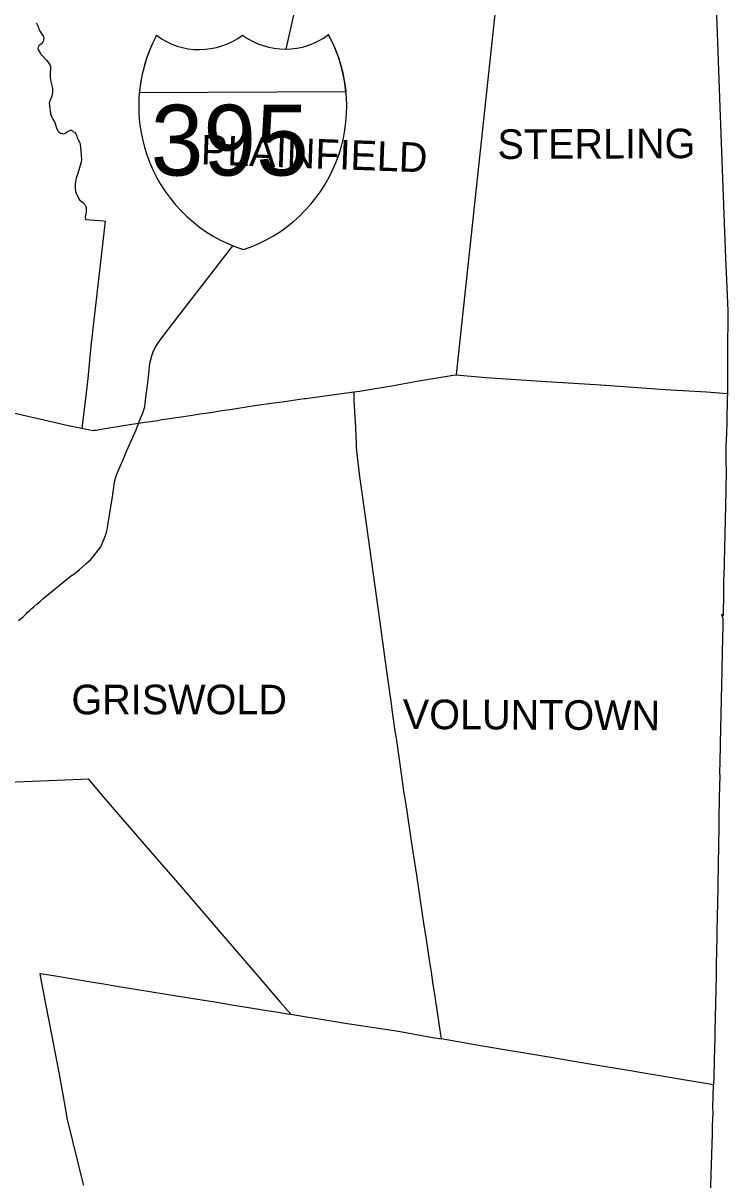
# Model space of a CAD drawing. Extents: x 0 to 2603, y -226 to 830.
# Drawn here: x 329.1 to 361.3, y 575 to 627.8 of the extents above; entities that cross this region are included whole.
import ezdxf

# ---------------------------------------------------------------- set-up
doc = ezdxf.new("R2010")
doc.units = 0
for name, color, linetype in [('CT_TSH_Map_Interstate_Roads', 7, 'Continuous'), ('CT_TSH_Map_Town_Limits', 7, 'Continuous'), ('CT_TSH_Map_Town_Text', 7, 'Continuous')]:
    doc.layers.add(name, color=color, linetype=linetype)

msp = doc.modelspace()

# ---------------------------------------------------------------- linework, layer by layer
at = {"layer": 'CT_TSH_Map_Interstate_Roads'}
msp.add_line((343.877, 624.637), (334.444, 624.598), dxfattribs=at)
for points in [[(341.147, 626.584), (341.673, 628.952), (341.736, 629.234), (341.778, 629.422), (341.809, 629.562)], [(334.875, 611.773), (334.931, 612.252), (334.964, 612.431), (335.01, 612.596), (335.073, 612.767), (335.132, 612.904), (335.198, 613.022), (335.3, 613.181), (335.65, 613.651), (338.704, 617.616)], [(334.718, 610.441), (334.815, 611.26), (334.875, 611.773)], [(334.617, 610.034), (334.694, 610.27), (334.718, 610.441)], [(333.36, 607.015), (333.42, 607.197), (333.748, 607.969), (333.882, 608.272), (334.099, 608.776), (334.3, 609.219), (334.451, 609.625), (334.497, 609.755), (334.586, 609.945), (334.617, 610.034)], [(333.2, 606.063), (333.252, 606.375), (333.278, 606.586), (333.3, 606.74), (333.36, 607.015)], [(333.078, 605.323), (333.2, 606.063)], [(332.989, 604.729), (333.013, 604.863)], [(333.013, 604.863), (333.078, 605.323)], [(332.712, 603.953), (332.795, 604.141), (332.894, 604.393), (332.95, 604.551), (332.989, 604.729)], [(331.465, 602.649), (331.714, 602.847), (332.019, 603.112), (332.217, 603.29), (332.367, 603.464), (332.682, 603.881), (332.712, 603.953)], [(330.474, 601.848), (331.198, 602.44)], [(331.198, 602.44), (331.354, 602.574), (331.383, 602.584)], [(331.383, 602.584), (331.465, 602.649)], [(329.901, 601.371), (330.05, 601.501), (330.474, 601.848)], [(329.298, 600.838), (329.349, 600.891), (329.428, 600.96), (329.541, 601.059), (329.631, 601.139)], [(329.631, 601.139), (329.785, 601.272)], [(329.785, 601.272), (329.901, 601.371)], [(328.928, 600.519), (329.144, 600.689), (329.181, 600.72), (329.298, 600.838)]]:
    msp.add_lwpolyline(points, dxfattribs=at)
for centre, radius, start, end in [((341.281, 623.978), 6.864, 151.8748, 252.2637), ((341.29, 623.974), 6.874, 151.8748, 174.7861), ((337.182, 629.83), 3.265, 233.2263, 307.1377), ((341.099, 629.848), 3.264, 233.3979, 307.1378), ((337.038, 623.958), 6.864, 288.272, 28.6609), ((337.047, 623.954), 6.864, 5.7168, 28.6609)]:
    msp.add_arc(centre, radius, start, end, dxfattribs=at)
at = {"layer": 'CT_TSH_Map_Town_Limits'}
for points in [[(360.247, 642.422), (360.282, 641.586), (360.297, 641.436), (360.382, 638.912), (360.476, 636.7), (360.573, 634.07), (360.626, 632.595), (360.674, 630.705), (360.925, 623.943), (361.148, 617.86), (361.184, 617.067), (361.24, 615.712), (361.288, 614.642), (361.267, 612.67), (361.271, 612.118), (361.268, 611.721), (361.271, 611.425), (361.264, 610.854)], [(351.958, 641.006), (351.841, 639.872), (351.725, 638.728), (351.597, 637.349), (351.525, 636.595), (351.059, 631.882), (348.901, 611.736), (348.901, 611.705)], [(329.735, 627.773), (329.778, 627.709), (329.823, 627.614), (329.859, 627.499), (329.914, 627.385), (330.056, 627.176), (330.072, 627.148), (330.083, 627.118), (330.087, 627.084), (330.081, 627.008), (330.062, 626.949), (330.05, 626.918), (330.005, 626.857), (329.975, 626.827), (329.878, 626.748), (329.862, 626.729), (329.831, 626.668), (329.821, 626.62), (329.864, 626.51), (329.939, 626.379), (329.973, 626.33), (330.005, 626.306), (330.219, 626.066), (330.333, 625.918), (330.379, 625.834), (330.395, 625.788), (330.395, 625.75), (330.397, 625.679), (330.377, 625.488), (330.382, 625.291), (330.408, 625.111), (330.472, 624.87), (330.486, 624.785), (330.489, 624.712), (330.481, 624.577), (330.445, 624.414), (330.432, 624.378), (330.362, 624.242), (330.34, 624.174), (330.331, 624.105), (330.342, 624.016), (330.368, 623.857), (330.37, 623.776), (330.391, 623.638), (330.418, 623.552), (330.452, 623.475), (330.494, 623.395), (330.571, 623.269), (330.594, 623.224), (330.654, 623.042), (330.665, 622.999), (330.732, 622.854), (330.771, 622.808), (330.855, 622.755), (330.934, 622.728), (330.98, 622.723), (331.028, 622.734), (331.153, 622.806), (331.237, 622.864), (331.299, 622.884), (331.326, 622.887), (331.358, 622.882), (331.38, 622.863), (331.481, 622.796), (331.511, 622.772), (331.552, 622.721), (331.567, 622.695), (331.596, 622.614), (331.615, 622.549)], [(331.615, 622.549), (331.628, 622.51), (331.662, 622.439), (331.721, 622.337), (331.732, 622.312), (331.744, 622.241), (331.774, 621.927), (331.798, 621.751), (331.8, 621.536), (331.786, 621.445), (331.744, 621.268), (331.716, 621.162), (331.678, 621.063), (331.602, 620.82), (331.578, 620.776), (331.526, 620.53), (331.513, 620.409), (331.514, 620.245), (331.54, 620.086), (331.562, 620.011), (331.634, 619.841), (331.668, 619.782), (331.722, 619.716), (331.777, 619.665), (331.862, 619.582), (331.901, 619.549), (331.954, 619.496), (331.991, 619.439), (332.006, 619.4), (332.017, 619.359), (332.02, 619.228), (332.013, 619.192), (332.013, 619.152), (331.984, 619.008), (331.974, 618.925), (331.986, 618.83), (331.999, 618.815), (332.199, 618.801), (332.817, 618.747), (332.884, 618.742), (332.235, 613.038), (332.092, 611.555), (332.012, 610.897), (331.819, 609.272)], [(348.901, 611.705), (348.668, 611.674), (347.108, 611.421), (345.963, 611.207), (345.586, 611.144), (345.02, 611.05), (344.486, 610.965), (344.221, 610.931)], [(361.264, 610.854), (360.314, 610.927), (358.428, 611.045), (355.488, 611.249), (353.765, 611.357), (353, 611.407), (350.252, 611.589), (348.901, 611.705)], [(344.221, 610.931), (343.236, 610.796), (342.019, 610.627), (341.964, 610.622), (341.371, 610.537), (340.957, 610.475), (340.564, 610.425), (339.703, 610.305), (338.592, 610.132), (338.451, 610.107), (338.122, 610.062), (337.794, 610.012), (337.581, 609.977), (337.205, 609.926), (336.876, 609.87), (336.248, 609.774), (335.707, 609.695), (335.473, 609.665), (335.294, 609.633), (334.948, 609.587), (334.843, 609.568), (334.675, 609.545), (334.607, 609.53), (333.816, 609.408), (332.886, 609.256), (332.612, 609.219), (332.489, 609.192), (332.406, 609.181), (332.349, 609.179), (332.322, 609.167), (332.193, 609.196), (331.819, 609.272)], [(344.221, 610.931), (344.233, 610.597), (344.233, 610.57), (344.273, 609.792), (344.282, 609.604), (344.328, 608.624), (344.336, 608.422), (344.367, 608.13), (344.478, 607.193), (344.599, 606.346), (344.863, 604.379), (345.412, 600.438), (345.689, 598.419), (345.941, 596.615), (345.965, 596.458), (346.103, 595.463), (346.123, 595.314), (346.167, 595.047), (346.406, 593.414), (346.5, 592.734), (346.579, 592.211), (346.641, 591.819), (346.843, 590.446), (347.081, 588.893), (347.223, 587.956), (347.424, 586.594), (347.511, 586.063), (347.674, 584.927), (347.748, 584.47), (347.829, 583.916), (347.919, 583.371), (347.969, 583.009), (347.978, 582.966), (348.14, 581.919), (348.199, 581.526), (348.215, 581.431)], [(361.264, 610.854), (361.26, 610.66), (361.245, 609.601), (361.226, 609.048), (361.198, 608.468), (361.199, 607.756), (361.215, 607.389), (361.198, 606.42), (361.134, 603.814), (361.133, 603.659), (361.122, 603.336), (361.122, 603.246), (361.113, 603.031), (361.085, 602.306), (361.093, 601.638), (361.076, 600.864), (361.07, 600.75), (361.004, 600.795), (361.061, 600.619), (361.056, 600.343), (361.051, 600.299), (361.052, 600.259), (361.045, 599.73), (361.027, 599.071), (361.016, 598.301), (361.02, 598.235), (361.013, 598.16), (360.995, 597.582), (360.94, 594.927), (360.94, 594.8), (360.926, 594.084), (360.909, 593.563), (360.909, 593.519), (360.917, 593.473), (360.89, 592.403), (360.876, 591.455), (360.871, 590.769), (360.866, 590.526), (360.841, 589.104), (360.835, 588.739), (360.83, 588.335), (360.79, 586.324), (360.783, 586.087), (360.755, 584.806), (360.752, 584.618), (360.752, 584.327), (360.696, 581.744), (360.688, 581.369), (360.683, 581.063), (360.648, 579.716), (360.635, 579.336)], [(331.819, 609.272), (331.192, 609.393), (330.826, 609.484), (328.229, 610.085)], [(325.906, 593.043), (326.547, 593.076), (327.314, 593.1), (329.577, 593.191), (331.802, 593.271), (332.109, 593.286), (332.428, 592.906), (332.726, 592.569), (335.142, 589.762), (336.091, 588.665), (338.483, 585.886), (339.715, 584.457), (340.889, 583.091), (341.356, 582.551)], [(331.898, 574.749), (331.892, 574.788), (331.165, 577.753), (330.968, 578.884), (330.872, 579.384), (330.781, 579.888), (330.346, 582.176), (330.166, 583.1), (329.937, 584.312), (329.922, 584.418), (330.537, 584.314), (332.324, 584.014), (332.824, 583.938), (333.334, 583.851), (336.133, 583.399), (337.578, 583.163), (337.811, 583.132), (338.666, 582.985), (340.364, 582.709), (340.772, 582.646), (341.204, 582.573), (341.356, 582.551)], [(341.356, 582.551), (342.244, 582.404), (342.557, 582.358), (343.84, 582.145), (346.261, 581.774), (347.746, 581.511), (348.215, 581.431)], [(360.635, 579.336), (357.185, 579.906), (356.938, 579.948), (356.462, 580.03), (355.355, 580.21), (354.442, 580.364), (353.215, 580.578), (350.097, 581.102), (348.215, 581.431)], [(360.442, 572.459), (360.525, 575.194), (360.524, 575.231), (360.582, 577.082), (360.59, 577.447), (360.605, 577.791), (360.612, 578.041), (360.608, 578.305), (360.635, 579.336)]]:
    msp.add_lwpolyline(points, dxfattribs=at)

# ---------------------------------------------------------------- texts
at = {"layer": 'CT_TSH_Map_Interstate_Roads'}
msp.add_text('395', height=3.2278, dxfattribs=at).set_placement((334.965, 620.818))
at = {"layer": 'CT_TSH_Map_Town_Text'}
for s, rotation, p in [('STERLING', 0.2317, (350.782, 621.572)), ('PLAINFIELD', 357.9408, (337.236, 621.33)), ('VOLUNTOWN', 359.7319, (346.46, 595.566))]:
    msp.add_text(s, height=1.35, rotation=rotation, dxfattribs=at).set_placement(p)
msp.add_text('GRISWOLD', height=1.35, dxfattribs=at).set_placement((331.347, 596.237))

doc.saveas('drawing.dxf')
